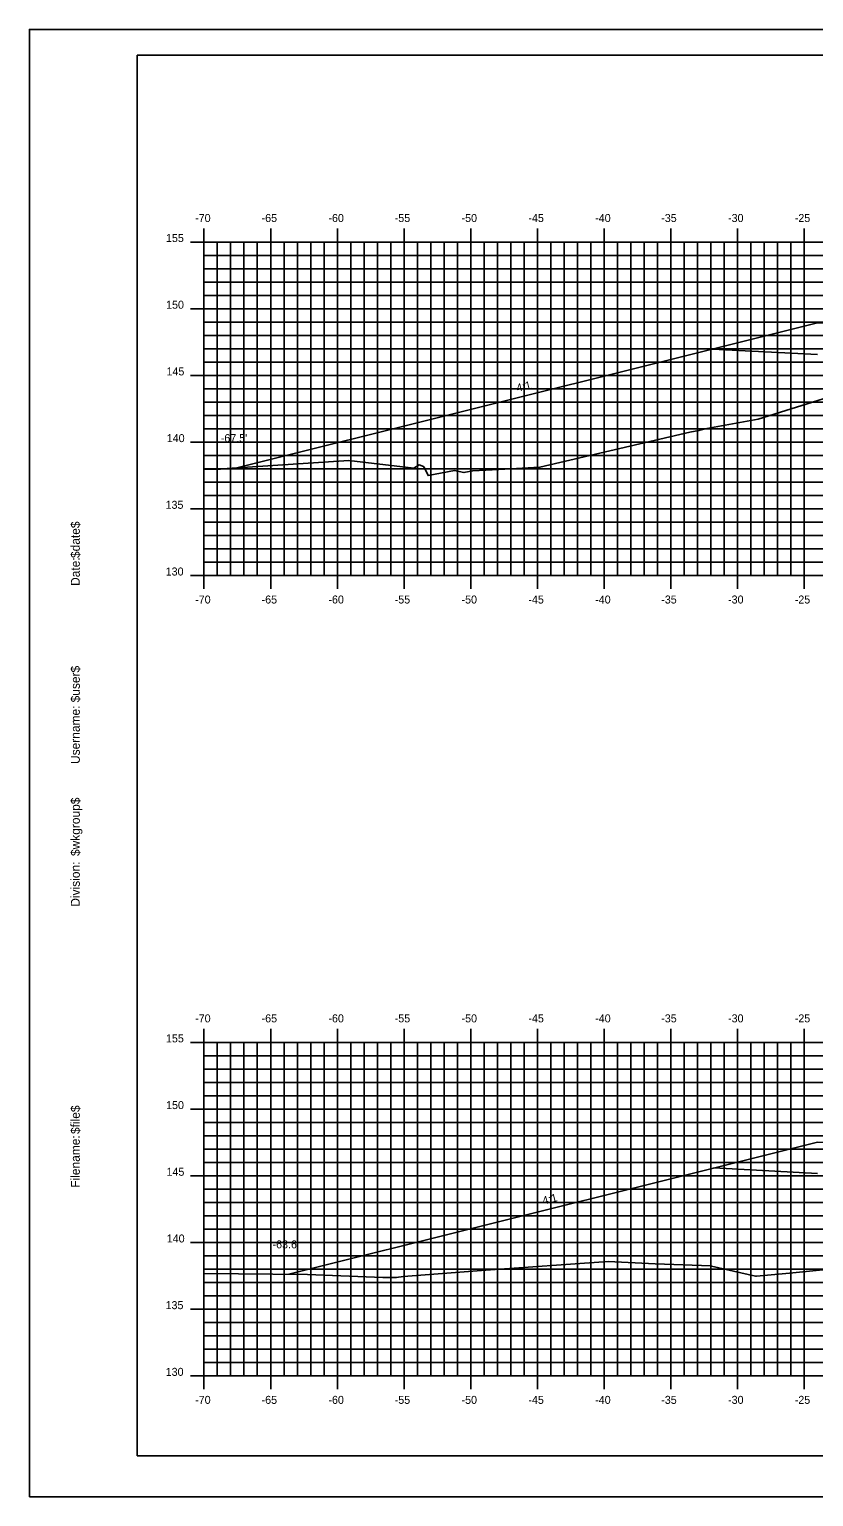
# Model space of a CAD drawing. Extents: x 851860 to 852032, y 365876 to 365986.
# Drawn here: x 851860.3 to 851919.1, y 365875.8 to 365985.8 of the extents above; entities that cross this region are included whole.
import ezdxf

# ---------------------------------------------------------------- set-up
doc = ezdxf.new("R2010")
doc.units = 0
for name, color, linetype in [('ANNOTATION', 7, 'Continuous'), ('BORDER', 7, 'Continuous'), ('D_Roadway_Centerline', 7, 'Continuous'), ('D_Roadway_FinishedGrade', 7, 'Continuous'), ('D_Roadway_SlopeLines', 7, 'Continuous'), ('D_Text_Standard', 7, 'Continuous'), ('H_V ANNOTATION', 7, 'Continuous'), ('MAJOR', 7, 'Continuous'), ('MINOR', 7, 'Continuous'), ('PLOT BOUNDARY', 7, 'Continuous'), ('S_Roadway_Centerline', 7, 'Continuous')]:
    doc.layers.add(name, color=color, linetype=linetype)

msp = doc.modelspace()

# ---------------------------------------------------------------- linework, layer by layer
at = {"layer": 'BORDER'}
msp.add_lwpolyline([(851868.41, 365878.83), (852028.41, 365878.83), (852028.41, 365983.83), (851868.41, 365983.83)], close=True, dxfattribs=at)
at = {"layer": 'D_Roadway_Centerline'}
for points in [[(851875.88, 365952.89), (851909.41, 365961.28), (851919.41, 365963.78), (851943.41, 365962.57), (851948.97, 365961.18)], [(851879.78, 365892.46), (851909.41, 365899.86), (851919.41, 365902.36), (851943.41, 365901.07), (851953.41, 365898.57), (851956.6, 365897.77)]]:
    msp.add_lwpolyline(points, dxfattribs=at)
at = {"layer": 'D_Roadway_FinishedGrade'}
for p, q in [((851919.41, 365961.41), (851911.53, 365961.81)), ((851919.41, 365900), (851911.63, 365900.42))]:
    msp.add_line(p, q, dxfattribs=at)
at = {"layer": 'D_Roadway_SlopeLines'}
for points in [[(851919.41, 365963.78), (851909.41, 365961.28), (851875.88, 365952.89)], [(851919.41, 365902.36), (851909.41, 365899.86), (851879.78, 365892.46)]]:
    msp.add_lwpolyline(points, dxfattribs=at)
at = {"layer": 'MAJOR'}
for p, q in [((851873.41, 365970.84), (851873.41, 365969.83)), ((851878.41, 365970.84), (851878.41, 365969.83)), ((851883.41, 365970.84), (851883.41, 365969.83)), ((851888.41, 365970.84), (851888.41, 365969.83)), ((851893.41, 365970.84), (851893.41, 365969.83)), ((851898.41, 365970.84), (851898.41, 365969.83)), ((851903.41, 365970.84), (851903.41, 365969.83)), ((851908.41, 365970.84), (851908.41, 365969.83)), ((851913.41, 365970.84), (851913.41, 365969.83)), ((851918.41, 365970.84), (851918.41, 365969.83)), ((851872.41, 365969.83), (851873.41, 365969.83)), ((851873.41, 365969.83), (852013.41, 365969.83)), ((851873.41, 365944.83), (851873.41, 365969.83)), ((851873.41, 365944.83), (851873.41, 365969.83)), ((851873.41, 365969.83), (852013.41, 365969.83)), ((851878.41, 365944.83), (851878.41, 365969.83)), ((851883.41, 365944.83), (851883.41, 365969.83)), ((851888.41, 365944.83), (851888.41, 365969.83)), ((851893.41, 365944.83), (851893.41, 365969.83)), ((851898.41, 365944.83), (851898.41, 365969.83)), ((851903.41, 365944.83), (851903.41, 365969.83)), ((851908.41, 365944.83), (851908.41, 365969.83)), ((851913.41, 365944.83), (851913.41, 365969.83)), ((851918.41, 365944.83), (851918.41, 365969.83)), ((851872.41, 365964.83), (851873.41, 365964.83)), ((851873.41, 365964.83), (852013.41, 365964.83)), ((851872.41, 365959.83), (851873.41, 365959.83)), ((851873.41, 365959.83), (852013.41, 365959.83)), ((851872.41, 365954.83), (851873.41, 365954.83)), ((851873.41, 365954.83), (852013.41, 365954.83)), ((851872.41, 365949.83), (851873.41, 365949.83)), ((851873.41, 365949.83), (852013.41, 365949.83)), ((851872.41, 365944.83), (851873.41, 365944.83)), ((851873.41, 365944.83), (852013.41, 365944.83)), ((851873.41, 365944.83), (852013.41, 365944.83)), ((851873.41, 365943.83), (851873.41, 365944.83)), ((851878.41, 365943.83), (851878.41, 365944.83)), ((851883.41, 365943.83), (851883.41, 365944.83)), ((851888.41, 365943.83), (851888.41, 365944.83)), ((851893.41, 365943.83), (851893.41, 365944.83)), ((851898.41, 365943.83), (851898.41, 365944.83)), ((851903.41, 365943.83), (851903.41, 365944.83)), ((851908.41, 365943.83), (851908.41, 365944.83)), ((851913.41, 365943.83), (851913.41, 365944.83)), ((851918.41, 365943.83), (851918.41, 365944.83)), ((851873.41, 365910.84), (851873.41, 365909.83)), ((851878.41, 365910.84), (851878.41, 365909.83)), ((851883.41, 365910.84), (851883.41, 365909.83)), ((851888.41, 365910.84), (851888.41, 365909.83)), ((851893.41, 365910.84), (851893.41, 365909.83)), ((851898.41, 365910.84), (851898.41, 365909.83)), ((851903.41, 365910.84), (851903.41, 365909.83)), ((851908.41, 365910.84), (851908.41, 365909.83)), ((851913.41, 365910.84), (851913.41, 365909.83)), ((851918.41, 365910.84), (851918.41, 365909.83)), ((851872.41, 365909.83), (851873.41, 365909.83)), ((851873.41, 365909.83), (852013.41, 365909.83)), ((851873.41, 365884.83), (851873.41, 365909.83)), ((851873.41, 365884.83), (851873.41, 365909.83)), ((851873.41, 365909.83), (852013.41, 365909.83)), ((851878.41, 365884.83), (851878.41, 365909.83)), ((851883.41, 365884.83), (851883.41, 365909.83)), ((851888.41, 365884.83), (851888.41, 365909.83)), ((851893.41, 365884.83), (851893.41, 365909.83)), ((851898.41, 365884.83), (851898.41, 365909.83)), ((851903.41, 365884.83), (851903.41, 365909.83)), ((851908.41, 365884.83), (851908.41, 365909.83)), ((851913.41, 365884.83), (851913.41, 365909.83)), ((851918.41, 365884.83), (851918.41, 365909.83)), ((851872.41, 365904.83), (851873.41, 365904.83)), ((851873.41, 365904.83), (852013.41, 365904.83)), ((851872.41, 365899.83), (851873.41, 365899.83)), ((851873.41, 365899.83), (852013.41, 365899.83)), ((851872.41, 365894.83), (851873.41, 365894.83)), ((851873.41, 365894.83), (852013.41, 365894.83)), ((851872.41, 365889.83), (851873.41, 365889.83)), ((851873.41, 365889.83), (852013.41, 365889.83)), ((851872.41, 365884.83), (851873.41, 365884.83)), ((851873.41, 365884.83), (852013.41, 365884.83)), ((851873.41, 365884.83), (852013.41, 365884.83)), ((851873.41, 365883.83), (851873.41, 365884.83)), ((851878.41, 365883.83), (851878.41, 365884.83)), ((851883.41, 365883.83), (851883.41, 365884.83)), ((851888.41, 365883.83), (851888.41, 365884.83)), ((851893.41, 365883.83), (851893.41, 365884.83)), ((851898.41, 365883.83), (851898.41, 365884.83)), ((851903.41, 365883.83), (851903.41, 365884.83)), ((851908.41, 365883.83), (851908.41, 365884.83)), ((851913.41, 365883.83), (851913.41, 365884.83)), ((851918.41, 365883.83), (851918.41, 365884.83))]:
    msp.add_line(p, q, dxfattribs=at)
at = {"layer": 'MINOR'}
for p, q in [((851874.41, 365944.83), (851874.41, 365969.83)), ((851875.41, 365944.83), (851875.41, 365969.83)), ((851876.41, 365944.83), (851876.41, 365969.83)), ((851877.41, 365944.83), (851877.41, 365969.83)), ((851879.41, 365944.83), (851879.41, 365969.83)), ((851880.41, 365944.83), (851880.41, 365969.83)), ((851881.41, 365944.83), (851881.41, 365969.83)), ((851882.41, 365944.83), (851882.41, 365969.83)), ((851884.41, 365944.83), (851884.41, 365969.83)), ((851885.41, 365944.83), (851885.41, 365969.83)), ((851886.41, 365944.83), (851886.41, 365969.83)), ((851887.41, 365944.83), (851887.41, 365969.83)), ((851889.41, 365944.83), (851889.41, 365969.83)), ((851890.41, 365944.83), (851890.41, 365969.83)), ((851891.41, 365944.83), (851891.41, 365969.83)), ((851892.41, 365944.83), (851892.41, 365969.83)), ((851894.41, 365944.83), (851894.41, 365969.83)), ((851895.41, 365944.83), (851895.41, 365969.83)), ((851896.41, 365944.83), (851896.41, 365969.83)), ((851897.41, 365944.83), (851897.41, 365969.83)), ((851899.41, 365944.83), (851899.41, 365969.83)), ((851900.41, 365944.83), (851900.41, 365969.83)), ((851901.41, 365944.83), (851901.41, 365969.83)), ((851902.41, 365944.83), (851902.41, 365969.83)), ((851904.41, 365944.83), (851904.41, 365969.83)), ((851905.41, 365944.83), (851905.41, 365969.83)), ((851906.41, 365944.83), (851906.41, 365969.83)), ((851907.41, 365944.83), (851907.41, 365969.83)), ((851909.41, 365944.83), (851909.41, 365969.83)), ((851910.41, 365944.83), (851910.41, 365969.83)), ((851911.41, 365944.83), (851911.41, 365969.83)), ((851912.41, 365944.83), (851912.41, 365969.83)), ((851914.41, 365944.83), (851914.41, 365969.83)), ((851915.41, 365944.83), (851915.41, 365969.83)), ((851916.41, 365944.83), (851916.41, 365969.83)), ((851917.41, 365944.83), (851917.41, 365969.83)), ((851873.41, 365968.83), (852013.41, 365968.83)), ((851873.41, 365968.83), (851874.41, 365968.83)), ((851873.41, 365967.83), (852013.41, 365967.83)), ((851873.41, 365967.83), (851874.41, 365967.83)), ((851873.41, 365966.83), (852013.41, 365966.83)), ((851873.41, 365966.83), (851874.41, 365966.83)), ((851873.41, 365965.83), (852013.41, 365965.83)), ((851873.41, 365965.83), (851874.41, 365965.83)), ((851873.41, 365963.83), (852013.41, 365963.83)), ((851873.41, 365963.83), (851874.41, 365963.83)), ((851873.41, 365962.83), (852013.41, 365962.83)), ((851873.41, 365962.83), (851874.41, 365962.83)), ((851873.41, 365961.83), (852013.41, 365961.83)), ((851873.41, 365961.83), (851874.41, 365961.83)), ((851873.41, 365960.83), (852013.41, 365960.83)), ((851873.41, 365960.83), (851874.41, 365960.83)), ((851873.41, 365958.83), (852013.41, 365958.83)), ((851873.41, 365958.83), (851874.41, 365958.83)), ((851873.41, 365957.83), (852013.41, 365957.83)), ((851873.41, 365957.83), (851874.41, 365957.83)), ((851873.41, 365956.83), (852013.41, 365956.83)), ((851873.41, 365956.83), (851874.41, 365956.83)), ((851873.41, 365955.83), (852013.41, 365955.83)), ((851873.41, 365955.83), (851874.41, 365955.83)), ((851873.41, 365953.83), (852013.41, 365953.83)), ((851873.41, 365953.83), (851874.41, 365953.83)), ((851873.41, 365952.83), (852013.41, 365952.83)), ((851873.41, 365952.83), (851874.41, 365952.83)), ((851873.41, 365951.83), (852013.41, 365951.83)), ((851873.41, 365951.83), (851874.41, 365951.83)), ((851873.41, 365950.83), (852013.41, 365950.83)), ((851873.41, 365950.83), (851874.41, 365950.83)), ((851873.41, 365948.83), (852013.41, 365948.83)), ((851873.41, 365948.83), (851874.41, 365948.83)), ((851873.41, 365947.83), (852013.41, 365947.83)), ((851873.41, 365947.83), (851874.41, 365947.83)), ((851873.41, 365946.83), (852013.41, 365946.83)), ((851873.41, 365946.83), (851874.41, 365946.83)), ((851873.41, 365945.83), (852013.41, 365945.83)), ((851873.41, 365945.83), (851874.41, 365945.83)), ((851874.41, 365884.83), (851874.41, 365909.83)), ((851875.41, 365884.83), (851875.41, 365909.83)), ((851876.41, 365884.83), (851876.41, 365909.83)), ((851877.41, 365884.83), (851877.41, 365909.83)), ((851879.41, 365884.83), (851879.41, 365909.83)), ((851880.41, 365884.83), (851880.41, 365909.83)), ((851881.41, 365884.83), (851881.41, 365909.83)), ((851882.41, 365884.83), (851882.41, 365909.83)), ((851884.41, 365884.83), (851884.41, 365909.83)), ((851885.41, 365884.83), (851885.41, 365909.83)), ((851886.41, 365884.83), (851886.41, 365909.83)), ((851887.41, 365884.83), (851887.41, 365909.83)), ((851889.41, 365884.83), (851889.41, 365909.83)), ((851890.41, 365884.83), (851890.41, 365909.83)), ((851891.41, 365884.83), (851891.41, 365909.83)), ((851892.41, 365884.83), (851892.41, 365909.83)), ((851894.41, 365884.83), (851894.41, 365909.83)), ((851895.41, 365884.83), (851895.41, 365909.83)), ((851896.41, 365884.83), (851896.41, 365909.83)), ((851897.41, 365884.83), (851897.41, 365909.83)), ((851899.41, 365884.83), (851899.41, 365909.83)), ((851900.41, 365884.83), (851900.41, 365909.83)), ((851901.41, 365884.83), (851901.41, 365909.83)), ((851902.41, 365884.83), (851902.41, 365909.83)), ((851904.41, 365884.83), (851904.41, 365909.83)), ((851905.41, 365884.83), (851905.41, 365909.83)), ((851906.41, 365884.83), (851906.41, 365909.83)), ((851907.41, 365884.83), (851907.41, 365909.83)), ((851909.41, 365884.83), (851909.41, 365909.83)), ((851910.41, 365884.83), (851910.41, 365909.83)), ((851911.41, 365884.83), (851911.41, 365909.83)), ((851912.41, 365884.83), (851912.41, 365909.83)), ((851914.41, 365884.83), (851914.41, 365909.83)), ((851915.41, 365884.83), (851915.41, 365909.83)), ((851916.41, 365884.83), (851916.41, 365909.83)), ((851917.41, 365884.83), (851917.41, 365909.83)), ((851873.41, 365908.83), (852013.41, 365908.83)), ((851873.41, 365908.83), (851874.41, 365908.83)), ((851873.41, 365907.83), (852013.41, 365907.83)), ((851873.41, 365907.83), (851874.41, 365907.83)), ((851873.41, 365906.83), (852013.41, 365906.83)), ((851873.41, 365906.83), (851874.41, 365906.83)), ((851873.41, 365905.83), (852013.41, 365905.83)), ((851873.41, 365905.83), (851874.41, 365905.83)), ((851873.41, 365903.83), (852013.41, 365903.83)), ((851873.41, 365903.83), (851874.41, 365903.83)), ((851873.41, 365902.83), (852013.41, 365902.83)), ((851873.41, 365902.83), (851874.41, 365902.83)), ((851873.41, 365901.83), (852013.41, 365901.83)), ((851873.41, 365901.83), (851874.41, 365901.83)), ((851873.41, 365900.83), (852013.41, 365900.83)), ((851873.41, 365900.83), (851874.41, 365900.83)), ((851873.41, 365898.83), (852013.41, 365898.83)), ((851873.41, 365898.83), (851874.41, 365898.83)), ((851873.41, 365897.83), (852013.41, 365897.83)), ((851873.41, 365897.83), (851874.41, 365897.83)), ((851873.41, 365896.83), (852013.41, 365896.83)), ((851873.41, 365896.83), (851874.41, 365896.83)), ((851873.41, 365895.83), (852013.41, 365895.83)), ((851873.41, 365895.83), (851874.41, 365895.83)), ((851873.41, 365893.83), (852013.41, 365893.83)), ((851873.41, 365893.83), (851874.41, 365893.83)), ((851873.41, 365892.83), (852013.41, 365892.83)), ((851873.41, 365892.83), (851874.41, 365892.83)), ((851873.41, 365891.83), (852013.41, 365891.83)), ((851873.41, 365891.83), (851874.41, 365891.83)), ((851873.41, 365890.83), (852013.41, 365890.83)), ((851873.41, 365890.83), (851874.41, 365890.83)), ((851873.41, 365888.83), (852013.41, 365888.83)), ((851873.41, 365888.83), (851874.41, 365888.83)), ((851873.41, 365887.83), (852013.41, 365887.83)), ((851873.41, 365887.83), (851874.41, 365887.83)), ((851873.41, 365886.83), (852013.41, 365886.83)), ((851873.41, 365886.83), (851874.41, 365886.83)), ((851873.41, 365885.83), (852013.41, 365885.83)), ((851873.41, 365885.83), (851874.41, 365885.83))]:
    msp.add_line(p, q, dxfattribs=at)
at = {"layer": 'PLOT BOUNDARY'}
msp.add_lwpolyline([(851860.32, 365875.77), (852030.32, 365875.77), (852030.32, 365985.77), (851860.32, 365985.77)], close=True, dxfattribs=at)
at = {"layer": 'S_Roadway_Centerline'}
for points in [[(851873.41, 365952.77), (851874.6, 365952.79), (851874.64, 365952.8), (851874.77, 365952.82), (851884.26, 365953.45), (851889.14, 365952.88), (851889.54, 365953.13), (851889.87, 365952.99), (851889.98, 365952.84), (851890.21, 365952.32), (851892.19, 365952.7), (851892.9, 365952.54), (851893.56, 365952.68), (851895.51, 365952.77), (851898.6, 365952.94), (851909.84, 365955.57), (851910.52, 365955.7), (851911.12, 365955.84), (851914.95, 365956.55), (851924.37, 365959.51)], [(851873.41, 365892.51), (851881.16, 365892.44), (851886.81, 365892.21), (851887.82, 365892.2), (851888.36, 365892.29), (851894.53, 365892.76), (851903.71, 365893.4), (851907.24, 365893.22), (851911.42, 365893.08), (851911.47, 365893.06), (851913.66, 365892.56), (851914.76, 365892.31), (851914.82, 365892.3), (851917.31, 365892.54), (851920.06, 365892.8)]]:
    msp.add_lwpolyline(points, dxfattribs=at)

# ---------------------------------------------------------------- texts
at = {"layer": 'ANNOTATION'}
for p in [(851896.91, 365958.58), (851898.86, 365897.66)]:
    msp.add_text('4:1', height=0.6, rotation=14.0362, dxfattribs=at).set_placement(p)
at = {"layer": 'BORDER'}
for s, p in [('$date$', (851864.1, 365946.14)), ('Date:', (851864.1, 365944.05)), ('$user$', (851864.1, 365935.32)), ('Username:', (851864.1, 365930.7)), ('$wkgroup$', (851864.1, 365923.8)), ('Division:', (851864.1, 365920)), ('$file$', (851864.1, 365902.96)), ('Filename:', (851864.1, 365898.93))]:
    msp.add_text(s, height=0.67, rotation=90, dxfattribs=at).set_placement(p)
at = {"layer": 'D_Text_Standard'}
for s, p in [("-67.5'", (851874.67, 365954.83)), ("-63.6'", (851878.55, 365894.39))]:
    msp.add_text(s, height=0.6, dxfattribs=at).set_placement(p)
at = {"layer": 'H_V ANNOTATION'}
for s, p in [('-70', (851872.75, 365971.33)), ('-65', (851877.73, 365971.33)), ('-60', (851882.74, 365971.33)), ('-55', (851887.71, 365971.33)), ('-50', (851892.72, 365971.33)), ('-45', (851897.73, 365971.33)), ('-40', (851902.74, 365971.33)), ('-35', (851907.69, 365971.33)), ('-30', (851912.7, 365971.33)), ('-25', (851917.7, 365971.33)), ('155', (851870.56, 365969.83)), ('150', (851870.57, 365964.83)), ('145', (851870.6, 365959.83)), ('140', (851870.62, 365954.83)), ('135', (851870.53, 365949.83)), ('130', (851870.54, 365944.83)), ('-70', (851872.75, 365942.73)), ('-65', (851877.73, 365942.73)), ('-60', (851882.74, 365942.73)), ('-55', (851887.71, 365942.73)), ('-50', (851892.72, 365942.73)), ('-45', (851897.73, 365942.73)), ('-40', (851902.74, 365942.73)), ('-35', (851907.69, 365942.73)), ('-30', (851912.7, 365942.73)), ('-25', (851917.7, 365942.73)), ('-70', (851872.75, 365911.33)), ('-65', (851877.73, 365911.33)), ('-60', (851882.74, 365911.33)), ('-55', (851887.71, 365911.33)), ('-50', (851892.72, 365911.33)), ('-45', (851897.73, 365911.33)), ('-40', (851902.74, 365911.33)), ('-35', (851907.69, 365911.33)), ('-30', (851912.7, 365911.33)), ('-25', (851917.7, 365911.33)), ('155', (851870.56, 365909.83)), ('150', (851870.57, 365904.83)), ('145', (851870.6, 365899.83)), ('140', (851870.62, 365894.83)), ('135', (851870.53, 365889.83)), ('130', (851870.54, 365884.83)), ('-70', (851872.75, 365882.73)), ('-65', (851877.73, 365882.73)), ('-60', (851882.74, 365882.73)), ('-55', (851887.71, 365882.73)), ('-50', (851892.72, 365882.73)), ('-45', (851897.73, 365882.73)), ('-40', (851902.74, 365882.73)), ('-35', (851907.69, 365882.73)), ('-30', (851912.7, 365882.73)), ('-25', (851917.7, 365882.73))]:
    msp.add_text(s, height=0.6, dxfattribs=at).set_placement(p)
at = {"layer": 'MAJOR'}
for p in [(851873.41, 365944.83), (851873.41, 365884.83)]:
    msp.add_text('-', height=0.006, dxfattribs=at).set_placement(p)

doc.saveas('drawing.dxf')
